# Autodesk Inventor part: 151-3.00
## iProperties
Created: 2007-06
Part Number: 151-3.00
Document SubType Name: Modeling
Designer: btaylor
Density: 1 g/cm^3
Author: btaylor
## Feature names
1. Sweep1
2. Extrusion1
3. Extrusion2
4. Extrusion3
5. Extrusion4
6. Sweep2
7. Fillet1
8. Fillet2
9. Fillet3
10. Fillet4
11. Chamfer1
12. Chamfer2
